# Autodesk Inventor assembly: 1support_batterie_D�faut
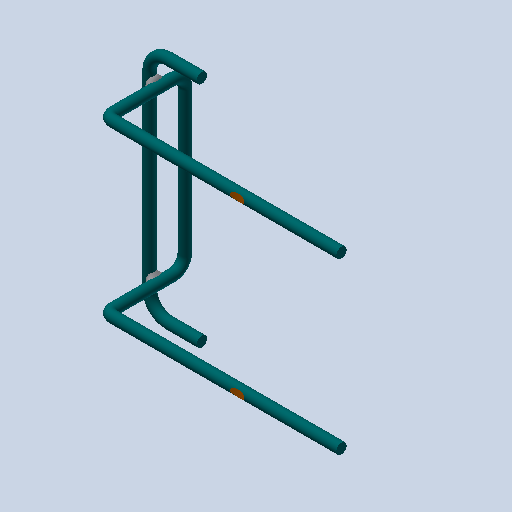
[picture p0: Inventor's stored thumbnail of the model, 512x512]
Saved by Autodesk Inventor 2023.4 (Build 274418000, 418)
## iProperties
Created: 2011-01
Part Number: 1support_batterie_D�faut
Document SubType Name: Assembly
Designer: eric
Mass: 42.3789 g
Surface Area: 218.745 cm^2
Volume: 42.3789 cm^3
Density: 1 g/cm^3
Author: eric
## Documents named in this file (5)
- C:\Users\bruno\Documents\1-Cours-2024-25\TSsI\7-Dynamique\chariot de golf\chariot_de_golf\chariot_de_golf_trolem\1support_batterie_Defaut.iam
- C:\Users\bruno\Documents\1-Cours-2024-25\TSsI\7-Dynamique\chariot de golf\chariot_de_golf\chariot_de_golf_trolem\bead13_Defaut.ipt
- C:\Users\bruno\Documents\1-Cours-2024-25\TSsI\7-Dynamique\chariot de golf\chariot_de_golf\chariot_de_golf_trolem\1rond_coude2_Defaut.ipt
- C:\Users\bruno\Documents\1-Cours-2024-25\TSsI\7-Dynamique\chariot de golf\chariot_de_golf\chariot_de_golf_trolem\bead12_Defaut.ipt
- C:\Users\bruno\Documents\1-Cours-2024-25\TSsI\7-Dynamique\chariot de golf\chariot_de_golf\chariot_de_golf_trolem\1rond_coude1_Defaut.ipt
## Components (4 placed, 4 different names)
1. bead13_Defaut:1
2. 1rond_coude2_Defaut:1
3. bead12_Defaut:1
4. 1rond_coude1_Defaut:1
